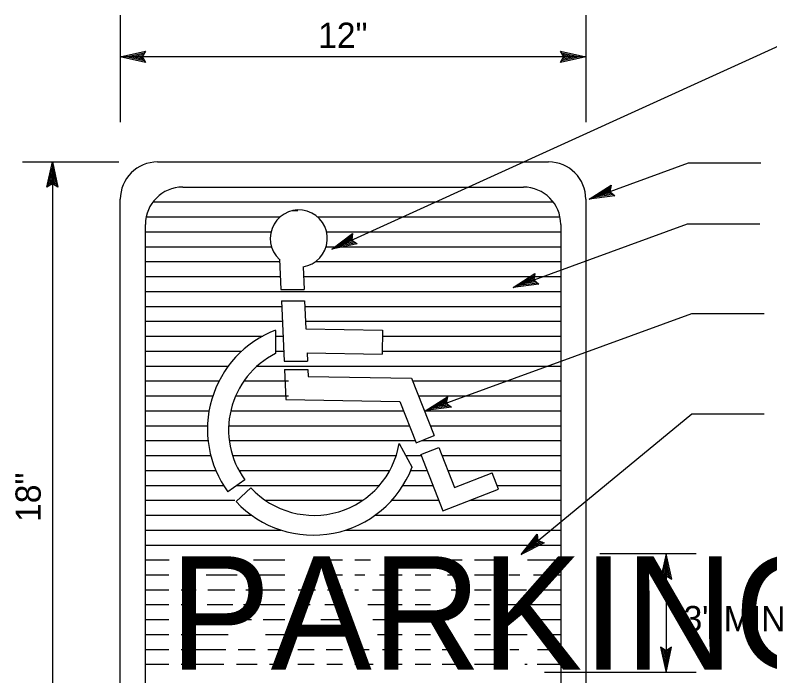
# Model space of a CAD drawing. Extents: x -121933 to -117742, y -103160 to -100084.
# Drawn here: x -118274.5 to -118094.9, y -101434.3 to -101277.1 of the extents above; entities that cross this region are included whole.
import ezdxf

# ---------------------------------------------------------------- set-up
doc = ezdxf.new("R2010")
doc.units = 0
for name, color, linetype in [('60 Nongeo Data', 7, 'Continuous'), ('G-MARK', 7, 'Continuous'), ('G-TEXT', 7, 'Continuous'), ('Misc CnstDet(22)', 7, 'Continuous')]:
    doc.layers.add(name, color=color, linetype=linetype)

msp = doc.modelspace()

# ---------------------------------------------------------------- linework, layer by layer
at = {"layer": '60 Nongeo Data'}
for p, q in [((-118240.6, -101312.06), (-118147.56, -101312.06)), ((-118234.61, -101318.05), (-118153.54, -101318.05)), ((-118249.47, -101468.31), (-118249.47, -101320.9)), ((-118138.69, -101320.93), (-118138.69, -101468.28)), ((-118241.71, -101321.59), (-118146.45, -101321.59)), ((-118208.52, -101323.59), (-118207.22, -101323.59)), ((-118243.3, -101325.14), (-118211.42, -101325.14)), ((-118202.57, -101325.14), (-118144.85, -101325.14)), ((-118243.48, -101462.3), (-118243.48, -101326.92)), ((-118144.67, -101326.92), (-118144.67, -101462.3)), ((-118243.48, -101328.69), (-118213.59, -101328.69)), ((-118200.4, -101328.69), (-118144.67, -101328.69)), ((-118243.48, -101332.24), (-118213.49, -101332.24)), ((-118200.49, -101332.24), (-118144.67, -101332.24)), ((-118243.48, -101335.78), (-118211.58, -101335.78)), ((-118211.62, -101335.25), (-118211.62, -101335.25)), ((-118211.61, -101335.18), (-118211.27, -101342.44)), ((-118203.02, -101335.78), (-118144.67, -101335.78)), ((-118205.97, -101336.99), (-118205.72, -101342.44)), ((-118243.48, -101339.33), (-118211.41, -101339.33)), ((-118205.87, -101339.33), (-118144.67, -101339.33)), ((-118243.48, -101342.88), (-118144.67, -101342.88)), ((-118211.27, -101342.44), (-118205.72, -101342.44)), ((-118243.48, -101346.43), (-118211.08, -101346.43)), ((-118211.14, -101345.14), (-118205.63, -101345.13)), ((-118211.14, -101345.14), (-118210.48, -101359.48)), ((-118205.6, -101345.13), (-118205.29, -101351.73)), ((-118205.54, -101346.43), (-118144.67, -101346.43)), ((-118243.48, -101349.97), (-118210.92, -101349.97)), ((-118205.37, -101349.97), (-118144.67, -101349.97)), ((-118205.29, -101351.73), (-118187.11, -101352.08)), ((-118243.48, -101353.52), (-118215.59, -101353.52)), ((-118212.52, -101352.12), (-118212.52, -101357.62)), ((-118212.52, -101353.52), (-118210.75, -101353.52)), ((-118187.11, -101352.08), (-118187.12, -101357.78)), ((-118187.11, -101353.52), (-118144.67, -101353.52)), ((-118243.48, -101357.07), (-118220.56, -101357.07)), ((-118212.52, -101357.07), (-118210.59, -101357.07)), ((-118187.12, -101357.07), (-118144.67, -101357.07)), ((-118205.02, -101357.44), (-118187.12, -101357.78)), ((-118205.02, -101357.44), (-118204.93, -101359.48)), ((-118243.48, -101360.61), (-118223.76, -101360.61)), ((-118216.91, -101360.61), (-118144.67, -101360.61)), ((-118210.49, -101359.48), (-118204.93, -101359.48)), ((-118210.39, -101361.41), (-118210.05, -101368.55)), ((-118210.39, -101361.41), (-118204.84, -101361.41)), ((-118204.84, -101361.41), (-118204.76, -101363.06)), ((-118243.48, -101364.16), (-118225.96, -101364.16)), ((-118220.05, -101364.16), (-118209.43, -101364.16)), ((-118204.76, -101363.06), (-118180.21, -101363.53)), ((-118180.21, -101363.53), (-118174.81, -101377.16)), ((-118179.95, -101364.16), (-118144.67, -101364.16)), ((-118243.48, -101367.71), (-118227.45, -101367.71)), ((-118222.03, -101367.71), (-118209.43, -101367.71)), ((-118178.55, -101367.71), (-118144.67, -101367.71)), ((-118210.05, -101368.55), (-118182.98, -101369.07)), ((-118182.98, -101369.07), (-118179.1, -101378.86)), ((-118243.48, -101371.26), (-118228.35, -101371.26)), ((-118223.19, -101371.26), (-118182.11, -101371.26)), ((-118177.15, -101371.26), (-118144.67, -101371.26)), ((-118243.48, -101374.8), (-118228.72, -101374.8)), ((-118223.68, -101374.8), (-118180.71, -101374.8)), ((-118175.74, -101374.8), (-118144.67, -101374.8)), ((-118243.48, -101378.35), (-118228.58, -101378.35)), ((-118223.54, -101378.35), (-118179.31, -101378.35)), ((-118179.1, -101378.86), (-118174.81, -101377.16)), ((-118177.82, -101378.35), (-118144.67, -101378.35)), ((-118183.1, -101379.01), (-118180.05, -101384.76)), ((-118177.99, -101381.67), (-118173.7, -101379.97)), ((-118173.7, -101379.97), (-118169.92, -101389.51)), ((-118243.48, -101381.9), (-118227.94, -101381.9)), ((-118222.76, -101381.9), (-118183.8, -101381.9)), ((-118181.57, -101381.9), (-118177.9, -101381.9)), ((-118177.99, -101381.67), (-118172.69, -101395.06)), ((-118172.94, -101381.9), (-118144.67, -101381.9)), ((-118243.48, -101385.45), (-118226.74, -101385.45)), ((-118221.26, -101385.45), (-118185.33, -101385.45)), ((-118180.33, -101385.45), (-118176.5, -101385.45)), ((-118171.53, -101385.45), (-118144.67, -101385.45)), ((-118169.92, -101389.51), (-118160.98, -101386.03)), ((-118159.47, -101389.92), (-118160.98, -101386.03)), ((-118219.87, -101387.67), (-118223.86, -101390.53)), ((-118243.48, -101388.99), (-118224.9, -101388.99)), ((-118218.41, -101389.58), (-118221.91, -101392.84)), ((-118221.71, -101388.99), (-118187.79, -101388.99)), ((-118182.17, -101388.99), (-118175.1, -101388.99)), ((-118159.82, -101388.99), (-118144.67, -101388.99)), ((-118172.69, -101395.06), (-118159.47, -101389.92)), ((-118243.48, -101392.54), (-118222.22, -101392.54)), ((-118214.97, -101392.54), (-118191.76, -101392.54)), ((-118184.85, -101392.54), (-118173.69, -101392.54)), ((-118166.22, -101392.54), (-118144.67, -101392.54)), ((-118243.48, -101396.09), (-118218.26, -101396.09)), ((-118188.82, -101396.09), (-118144.67, -101396.09)), ((-118243.48, -101399.63), (-118211.23, -101399.63)), ((-118195.85, -101399.63), (-118144.67, -101399.63)), ((-118243.48, -101403.18), (-118144.67, -101403.18)), ((-118243.48, -101406.73), (-118237.86, -101406.73)), ((-118230.83, -101406.73), (-118221.1, -101406.73)), ((-118217.78, -101406.73), (-118210.28, -101406.73)), ((-118202.25, -101406.73), (-118196.56, -101406.73)), ((-118193.64, -101406.73), (-118189.93, -101406.73)), ((-118186.53, -101406.73), (-118182.42, -101406.73)), ((-118179.33, -101406.73), (-118175.69, -101406.73)), ((-118172.59, -101406.73), (-118168.14, -101406.73)), ((-118165.17, -101406.73), (-118158.63, -101406.73)), ((-118152.57, -101406.73), (-118144.67, -101406.73)), ((-118243.48, -101410.28), (-118237.89, -101410.28)), ((-118229.04, -101410.28), (-118221.64, -101410.28)), ((-118217.08, -101410.28), (-118210.28, -101410.28)), ((-118200.38, -101410.28), (-118196.56, -101410.28)), ((-118193.64, -101410.28), (-118191.32, -101410.28)), ((-118187.79, -101410.28), (-118182.42, -101410.28)), ((-118179.33, -101410.28), (-118175.56, -101410.28)), ((-118171.63, -101410.28), (-118168.05, -101410.28)), ((-118165.17, -101410.28), (-118160.37, -101410.28)), ((-118157.02, -101410.28), (-118154.4, -101410.28)), ((-118151.17, -101410.28), (-118144.67, -101410.28)), ((-118243.48, -101413.82), (-118237.89, -101413.82)), ((-118234.97, -101413.82), (-118231.44, -101413.82)), ((-118228.64, -101413.82), (-118222.18, -101413.82)), ((-118219.61, -101413.82), (-118219, -101413.82)), ((-118216.52, -101413.82), (-118210.28, -101413.82)), ((-118207.18, -101413.82), (-118203.04, -101413.82)), ((-118200.16, -101413.82), (-118196.56, -101413.82)), ((-118193.64, -101413.82), (-118192.76, -101413.82)), ((-118189.45, -101413.82), (-118182.42, -101413.82)), ((-118179.33, -101413.82), (-118175.64, -101413.82)), ((-118170.71, -101413.82), (-118168.1, -101413.82)), ((-118165.17, -101413.82), (-118161.2, -101413.82)), ((-118158.28, -101413.82), (-118152.83, -101413.82)), ((-118150.52, -101413.82), (-118144.67, -101413.82)), ((-118243.48, -101417.37), (-118237.89, -101417.37)), ((-118234.97, -101417.37), (-118231.92, -101417.37)), ((-118228.82, -101417.37), (-118222.72, -101417.37)), ((-118220.14, -101417.37), (-118218.7, -101417.37)), ((-118216.08, -101417.37), (-118210.28, -101417.37)), ((-118207.18, -101417.37), (-118204.3, -101417.37)), ((-118200.81, -101417.37), (-118196.56, -101417.37)), ((-118190.54, -101417.37), (-118182.42, -101417.37)), ((-118179.33, -101417.37), (-118175.64, -101417.37)), ((-118169.8, -101417.37), (-118168.18, -101417.37)), ((-118165.17, -101417.37), (-118161.64, -101417.37)), ((-118158.8, -101417.37), (-118144.67, -101417.37)), ((-118243.48, -101420.92), (-118237.89, -101420.92)), ((-118229.78, -101420.92), (-118223.26, -101420.92)), ((-118220.53, -101420.92), (-118218.26, -101420.92)), ((-118215.51, -101420.92), (-118210.28, -101420.92)), ((-118201.73, -101420.92), (-118196.56, -101420.92)), ((-118189.4, -101420.92), (-118182.42, -101420.92)), ((-118179.33, -101420.92), (-118175.69, -101420.92)), ((-118172.94, -101420.92), (-118171.28, -101420.92)), ((-118165.17, -101420.92), (-118161.42, -101420.92)), ((-118158.76, -101420.92), (-118155.49, -101420.92)), ((-118150.25, -101420.92), (-118144.67, -101420.92)), ((-118243.48, -101424.47), (-118237.89, -101424.47)), ((-118235.01, -101424.47), (-118223.8, -101424.47)), ((-118214.95, -101424.47), (-118210.28, -101424.47)), ((-118207.31, -101424.47), (-118203.78, -101424.47)), ((-118200.64, -101424.47), (-118196.56, -101424.47)), ((-118188.23, -101424.47), (-118182.42, -101424.47)), ((-118179.33, -101424.47), (-118175.64, -101424.47)), ((-118172.85, -101424.47), (-118170.32, -101424.47)), ((-118165.17, -101424.47), (-118161.38, -101424.47)), ((-118158.24, -101424.47), (-118152.65, -101424.47)), ((-118150.25, -101424.47), (-118144.67, -101424.47)), ((-118243.48, -101428.01), (-118237.89, -101428.01)), ((-118235.01, -101428.01), (-118224.34, -101428.01)), ((-118221.4, -101428.01), (-118217.39, -101428.01)), ((-118214.38, -101428.01), (-118210.28, -101428.01)), ((-118207.23, -101428.01), (-118203.34, -101428.01)), ((-118200.46, -101428.01), (-118196.56, -101428.01)), ((-118193.64, -101428.01), (-118190.23, -101428.01)), ((-118187.09, -101428.01), (-118182.42, -101428.01)), ((-118179.33, -101428.01), (-118175.64, -101428.01)), ((-118172.85, -101428.01), (-118169.4, -101428.01)), ((-118165.17, -101428.01), (-118160.59, -101428.01)), ((-118156.75, -101428.01), (-118154.62, -101428.01)), ((-118150.21, -101428.01), (-118144.67, -101428.01)), ((-118243.48, -101431.56), (-118237.89, -101431.56)), ((-118235.01, -101431.56), (-118224.87, -101431.56)), ((-118221.84, -101431.56), (-118216.91, -101431.56)), ((-118213.99, -101431.56), (-118210.28, -101431.56)), ((-118207.23, -101431.56), (-118203.3, -101431.56)), ((-118200.33, -101431.56), (-118196.56, -101431.56)), ((-118193.64, -101431.56), (-118189.27, -101431.56)), ((-118185.96, -101431.56), (-118182.42, -101431.56)), ((-118179.33, -101431.56), (-118175.6, -101431.56)), ((-118172.85, -101431.56), (-118168.49, -101431.56)), ((-118165.17, -101431.56), (-118159.02, -101431.56)), ((-118153.22, -101431.56), (-118152.65, -101431.56)), ((-118150.25, -101431.56), (-118144.67, -101431.56))]:
    msp.add_line(p, q, dxfattribs=at)
for centre, radius, start, end in [((-118240.6, -101320.93), 8.87, 90, 180), ((-118147.56, -101320.93), 8.87, 0, 90), ((-118234.61, -101326.92), 8.87, 90, 180), ((-118153.54, -101326.92), 8.87, 0, 90), ((-118206.99, -101330.28), 6.79, 278.6354, 226.9819), ((-118203.54, -101375.64), 25.19, 110.8877, 216.2326), ((-118203.54, -101375.64), 25.19, 110.8877, 216.2354), ((-118203.35, -101375.79), 20.35, 116.7766, 215.7522), ((-118203.36, -101375.58), 20.55, 222.9271, 350.3849), ((-118203.54, -101375.64), 25.19, 223.0917, 338.7814), ((-118203.54, -101375.64), 25.19, 338.7814, 338.8071)]:
    msp.add_arc(centre, radius, start, end, dxfattribs=at)
at = {"layer": 'G-MARK'}
for p, q in [((-118138.71, -101287.06), (-118249.47, -101287.06)), ((-118265.63, -101312.06), (-118265.63, -101477.15)), ((-118119.61, -101405.32), (-118119.61, -101433.52))]:
    msp.add_line(p, q, dxfattribs=at)
for points in [[(-118199.11, -101332.81), (-118087.36, -101282.02), (-118070.17, -101282.02)], [(-118137.87, -101320.89), (-118114.24, -101312.26), (-118097.05, -101312.26)], [(-118155.99, -101341.93), (-118114.5, -101326.78), (-118097.31, -101326.78)], [(-118176.79, -101371.22), (-118113.49, -101348.12), (-118096.3, -101348.12)], [(-118154.1, -101405.41), (-118113.49, -101372.01), (-118096.3, -101372.01)]]:
    msp.add_lwpolyline(points, dxfattribs=at)
at = {"layer": 'G-TEXT'}
for p, q in [((-118249.47, -101287.06), (-118243.47, -101285.73)), ((-118243.47, -101288.4), (-118249.47, -101287.06)), ((-118249.47, -101287.06), (-118249.47, -101287.06)), ((-118243.68, -101288.05), (-118248.09, -101287.06)), ((-118248.08, -101287.06), (-118243.7, -101286.09)), ((-118246.7, -101287.06), (-118243.88, -101286.44)), ((-118243.92, -101287.69), (-118246.7, -101287.06)), ((-118245.32, -101287.06), (-118244.11, -101286.8)), ((-118244.09, -101287.34), (-118245.32, -101287.06)), ((-118243.47, -101285.73), (-118244.27, -101287.06)), ((-118244.27, -101287.06), (-118243.47, -101288.4)), ((-118243.47, -101285.73), (-118243.47, -101285.73)), ((-118143.91, -101287.06), (-118144.71, -101285.72)), ((-118144.71, -101285.72), (-118144.71, -101285.72)), ((-118144.71, -101285.72), (-118138.71, -101287.06)), ((-118138.71, -101287.06), (-118144.71, -101288.39)), ((-118144.71, -101288.39), (-118143.91, -101287.06)), ((-118144.49, -101286.08), (-118140.09, -101287.06)), ((-118140.1, -101287.06), (-118144.48, -101288.03)), ((-118141.47, -101287.06), (-118144.3, -101287.69)), ((-118144.26, -101286.44), (-118141.47, -101287.06)), ((-118144.08, -101286.78), (-118142.85, -101287.06)), ((-118142.85, -101287.06), (-118144.06, -101287.33)), ((-118138.71, -101287.06), (-118138.71, -101287.06)), ((-118243.47, -101288.4), (-118243.47, -101288.4)), ((-118144.71, -101288.39), (-118144.71, -101288.39)), ((-118266.97, -101318.06), (-118265.63, -101312.06)), ((-118265.63, -101312.06), (-118265.63, -101312.06)), ((-118265.63, -101312.06), (-118264.3, -101318.06)), ((-118266.62, -101317.84), (-118265.63, -101313.44)), ((-118265.63, -101313.45), (-118264.66, -101317.83)), ((-118266.26, -101317.61), (-118265.63, -101314.82)), ((-118265.63, -101314.82), (-118265.01, -101317.65)), ((-118265.63, -101317.26), (-118266.97, -101318.06)), ((-118265.91, -101317.43), (-118265.63, -101316.21)), ((-118265.63, -101316.21), (-118265.37, -101317.41)), ((-118264.3, -101318.06), (-118265.63, -101317.26)), ((-118137.87, -101320.89), (-118132.69, -101317.58)), ((-118132.69, -101317.58), (-118132.99, -101319.11)), ((-118132.69, -101317.58), (-118132.69, -101317.58)), ((-118266.97, -101318.06), (-118266.97, -101318.06)), ((-118264.3, -101318.06), (-118264.3, -101318.06)), ((-118136.57, -101320.41), (-118132.79, -101318)), ((-118135.28, -101319.94), (-118132.84, -101318.39)), ((-118132.45, -101319.57), (-118135.28, -101319.94)), ((-118133.98, -101319.47), (-118132.94, -101318.81)), ((-118132.73, -101319.31), (-118133.98, -101319.47)), ((-118132.99, -101319.11), (-118131.78, -101320.09)), ((-118131.78, -101320.09), (-118137.87, -101320.89)), ((-118137.87, -101320.89), (-118137.87, -101320.89)), ((-118132.1, -101319.83), (-118136.58, -101320.41)), ((-118131.78, -101320.09), (-118131.78, -101320.09)), ((-118199.11, -101332.81), (-118194.19, -101329.12)), ((-118197.84, -101332.23), (-118194.26, -101329.54)), ((-118196.59, -101331.67), (-118194.28, -101329.93)), ((-118195.33, -101331.1), (-118194.34, -101330.36)), ((-118194.19, -101329.12), (-118194.37, -101330.66)), ((-118194.19, -101329.12), (-118194.19, -101329.12)), ((-118193.09, -101331.55), (-118199.11, -101332.81)), ((-118193.43, -101331.32), (-118197.85, -101332.24)), ((-118193.79, -101331.09), (-118196.59, -101331.67)), ((-118194.1, -101330.84), (-118195.33, -101331.1)), ((-118194.37, -101330.66), (-118193.09, -101331.55)), ((-118193.09, -101331.55), (-118193.09, -101331.55)), ((-118199.11, -101332.81), (-118199.11, -101332.81)), ((-118155.99, -101341.93), (-118150.81, -101338.62)), ((-118154.68, -101341.45), (-118150.91, -101339.04)), ((-118153.39, -101340.98), (-118150.95, -101339.43)), ((-118150.81, -101338.62), (-118151.1, -101340.14)), ((-118150.81, -101338.62), (-118150.81, -101338.62)), ((-118149.89, -101341.13), (-118155.99, -101341.93)), ((-118150.22, -101340.87), (-118154.69, -101341.45)), ((-118150.56, -101340.61), (-118153.39, -101340.98)), ((-118152.1, -101340.51), (-118151.05, -101339.84)), ((-118150.85, -101340.35), (-118152.1, -101340.51)), ((-118151.1, -101340.14), (-118149.89, -101341.13)), ((-118149.89, -101341.13), (-118149.89, -101341.13)), ((-118155.99, -101341.93), (-118155.99, -101341.93)), ((-118176.79, -101371.22), (-118171.6, -101367.91)), ((-118171.6, -101367.91), (-118171.9, -101369.44)), ((-118171.6, -101367.91), (-118171.6, -101367.91)), ((-118175.48, -101370.74), (-118171.7, -101368.33)), ((-118174.19, -101370.27), (-118171.75, -101368.72)), ((-118171.36, -101369.9), (-118174.19, -101370.27)), ((-118172.89, -101369.8), (-118171.85, -101369.13)), ((-118171.64, -101369.64), (-118172.89, -101369.8)), ((-118171.9, -101369.44), (-118170.69, -101370.42)), ((-118170.69, -101370.42), (-118176.79, -101371.22)), ((-118176.79, -101371.22), (-118176.79, -101371.22)), ((-118171.02, -101370.16), (-118175.49, -101370.74)), ((-118170.69, -101370.42), (-118170.69, -101370.42)), ((-118154.1, -101405.41), (-118150.31, -101400.57)), ((-118153.03, -101404.53), (-118150.27, -101401)), ((-118151.97, -101403.66), (-118150.18, -101401.38)), ((-118150.9, -101402.78), (-118150.14, -101401.81)), ((-118149.78, -101402.21), (-118150.9, -101402.78)), ((-118150.31, -101400.58), (-118150.09, -101402.11)), ((-118150.31, -101400.58), (-118150.31, -101400.58)), ((-118150.09, -101402.11), (-118148.62, -101402.64)), ((-118148.62, -101402.64), (-118154.1, -101405.41)), ((-118149.01, -101402.5), (-118153.04, -101404.54)), ((-118149.42, -101402.37), (-118151.97, -101403.66)), ((-118148.62, -101402.64), (-118148.62, -101402.64)), ((-118154.1, -101405.41), (-118154.1, -101405.41)), ((-118119.61, -101405.32), (-118120.94, -101411.32)), ((-118118.27, -101411.32), (-118119.61, -101405.32)), ((-118119.61, -101405.32), (-118119.61, -101405.32)), ((-118119.61, -101406.71), (-118120.58, -101411.09)), ((-118118.62, -101411.1), (-118119.61, -101406.7)), ((-118119.61, -101408.08), (-118120.23, -101410.91)), ((-118119.6, -101409.46), (-118119.87, -101410.67)), ((-118118.98, -101410.87), (-118119.61, -101408.08)), ((-118119.33, -101410.69), (-118119.6, -101409.46)), ((-118120.94, -101411.32), (-118119.61, -101410.52)), ((-118119.61, -101410.52), (-118118.27, -101411.32)), ((-118120.94, -101411.32), (-118120.94, -101411.32)), ((-118118.27, -101411.32), (-118118.27, -101411.32)), ((-118119.61, -101428.32), (-118120.95, -101427.52)), ((-118120.95, -101427.52), (-118120.95, -101427.52)), ((-118120.95, -101427.52), (-118119.61, -101433.52)), ((-118120.59, -101427.74), (-118119.61, -101432.14)), ((-118120.23, -101427.97), (-118119.61, -101430.76)), ((-118119.89, -101428.15), (-118119.61, -101429.38)), ((-118119.61, -101433.52), (-118118.28, -101427.52)), ((-118118.28, -101427.52), (-118119.61, -101428.32)), ((-118119.61, -101430.76), (-118118.98, -101427.94)), ((-118119.61, -101429.38), (-118119.34, -101428.17)), ((-118119.6, -101432.13), (-118118.64, -101427.76)), ((-118118.28, -101427.52), (-118118.28, -101427.52)), ((-118119.61, -101433.52), (-118119.61, -101433.52))]:
    msp.add_line(p, q, dxfattribs=at)
at = {"layer": 'Misc CnstDet(22)'}
for p, q in [((-118249.47, -101277.14), (-118249.47, -101302.61)), ((-118138.71, -101277.14), (-118138.71, -101302.61)), ((-118272.73, -101312.06), (-118249.84, -101312.06)), ((-118112.48, -101405.32), (-118135.37, -101405.32)), ((-118112.48, -101433.52), (-118148.53, -101433.52))]:
    msp.add_line(p, q, dxfattribs=at)

# ---------------------------------------------------------------- texts
at = {"layer": '60 Nongeo Data'}
msp.add_text('PARKING', height=26.983, dxfattribs=at).set_placement((-118237.76, -101432.84))
at = {"layer": 'Misc CnstDet(22)'}
for s, rotation, p in [('12"', 0.168, (-118202.4, -101284.95)), ('18"', 90.168, (-118268.39, -101397.71)), ('3" MIN', 359.832, (-118115.45, -101423.67))]:
    msp.add_text(s, height=6, rotation=rotation, dxfattribs=at).set_placement(p)

doc.saveas('drawing.dxf')
